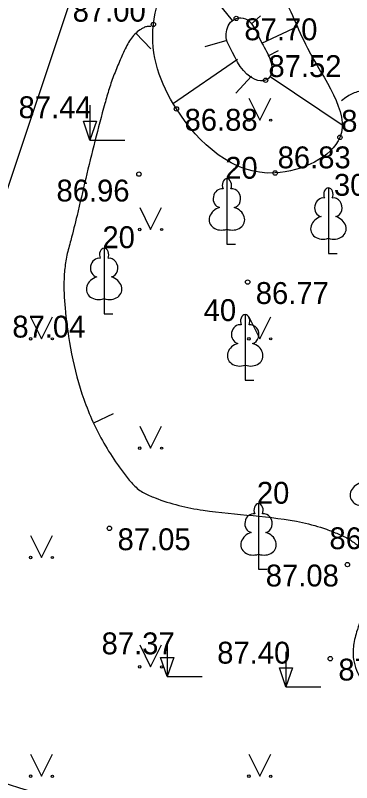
# Model space of a CAD drawing. Extents: x 576692 to 577659, y 273254 to 273799.
# Drawn here: x 577579.4 to 577587.1, y 273474.85 to 273492.4 of the extents above; entities that cross this region are included whole.
import ezdxf

# ---------------------------------------------------------------- set-up
doc = ezdxf.new("R2010")
doc.units = 0
for name, color, linetype in [('APGR_SARK_####_####_#', 7, 'Continuous'), ('CELI_TAKA_####_####_#', 7, 'Continuous'), ('GAZE_ELEM_####_####_#', 7, 'Continuous'), ('GEOD_SITP_####_TKST_#', 7, 'Continuous'), ('HIDT_REZV_####_TKST_#', 7, 'Continuous'), ('LKAN_ELEM_PAST_TKST_#', 7, 'Continuous'), ('RELJ_ELEM_####_####_#', 7, 'Continuous'), ('SAKT_ELEM_####_####_#', 7, 'Continuous')]:
    doc.layers.add(name, color=color, linetype=linetype)

msp = doc.modelspace()

# ---------------------------------------------------------------- linework, layer by layer
at = {"layer": 'CELI_TAKA_####_####_#'}
msp.add_lwpolyline([(577405.2, 273487.348), (577452.189, 273444.346), (577456.559, 273431.587), (577478.341, 273425.873), (577486.021, 273451.871), (577490.672, 273451.531), (577489.422, 273447.212), (577534.643, 273445.737), (577535.261, 273448.657), (577565.483, 273447.437), (577587.681, 273513.681), (577602.056, 273510.387), (577616.261, 273508.586), (577600.316, 273457.536), (577582.857, 273411.886)], dxfattribs=at)
at = {"layer": 'GAZE_ELEM_####_####_#'}
for p, q in [((577584.374, 273492.276), (577583.292, 273493.615)), ((577584.8, 273492.195), (577585.015, 273492.389)), ((577585.045, 273491.761), (577585.88, 273492.15)), ((577584.246, 273491.821), (577583.74, 273491.675)), ((577585.19, 273491.469), (577585.431, 273491.589)), ((577584.49, 273491.386), (577583.004, 273490.363)), ((577584.811, 273491.004), (577584.45, 273490.619)), ((577585.236, 273490.997), (577586.932, 273489.866))]:
    msp.add_line(p, q, dxfattribs=at)
msp.add_spline([(577585.045, 273491.761), (577584.946, 273491.975), (577584.674, 273492.316), (577584.461, 273492.327), (577584.3, 273492.194), (577584.24, 273491.842), (577584.324, 273491.65), (577584.896, 273490.928), (577585.132, 273490.912), (577585.246, 273491.014), (577585.246, 273491.356), (577585.045, 273491.761)], degree=3, dxfattribs=at)
at = {"layer": 'GEOD_SITP_####_TKST_#'}
for p, q in [((577582.507, 273491.629), (577582.162, 273491.991)), ((577581.644, 273483.285), (577581.19, 273483.075))]:
    msp.add_line(p, q, dxfattribs=at)
for points in [[(577583.144, 273499.137), (577583.833, 273498.666), (577584.196, 273498.357), (577584.348, 273498.172), (577584.469, 273497.968), (577584.689, 273497.451), (577584.886, 273496.935), (577585.096, 273496.425), (577585.352, 273495.926), (577585.521, 273495.668), (577585.622, 273495.549), (577585.742, 273495.438), (577586.297, 273495.12), (577586.897, 273494.983), (577587.193, 273494.971), (577587.489, 273494.982), (577587.785, 273494.998), (577588.081, 273495.001), (577588.596, 273494.934), (577589.109, 273494.81), (577589.619, 273494.7), (577589.872, 273494.672), (577589.999, 273494.669), (577590.125, 273494.674), (577590.318, 273494.721), (577590.408, 273494.77), (577590.494, 273494.839), (577590.628, 273495.017), (577590.683, 273495.217), (577590.755, 273496.357), (577590.811, 273497.592), (577590.863, 273497.846), (577590.914, 273497.968), (577590.98, 273498.087), (577591.132, 273498.277), (577591.322, 273498.418), (577591.659, 273498.578), (577592.004, 273498.713), (577592.357, 273498.812), (577592.717, 273498.865), (577594.021, 273498.804), (577594.245, 273498.727), (577594.465, 273498.642), (577594.895, 273498.449), (577597.047, 273497.335), (577597.802, 273496.866), (577597.99, 273496.746), (577598.086, 273496.7), (577598.186, 273496.683), (577598.881, 273496.773), (577599.58, 273496.97), (577600.282, 273497.202), (577600.635, 273497.308), (577600.988, 273497.397), (577601.285, 273497.465), (577601.582, 273497.54), (577602.177, 273497.692), (577602.774, 273497.816), (577603.075, 273497.858), (577603.378, 273497.881), (577603.698, 273497.87), (577603.769, 273497.867), (577603.904, 273497.862), (577603.97, 273497.851), (577604.035, 273497.824), (577604.253, 273497.675), (577604.447, 273497.506), (577604.75, 273497.093), (577605.115, 273496.124), (577605.373, 273495.082), (577605.539, 273494.584), (577605.77, 273494.129), (577606.025, 273493.738), (577606.322, 273493.373), (577606.563, 273493.171), (577606.832, 273493.008), (577607.412, 273492.744), (577607.99, 273492.479), (577608.254, 273492.316), (577608.489, 273492.114), (577608.663, 273491.921), (577608.845, 273491.698), (577610.478, 273490.111)], [(577582.506, 273492.14), (577582.477, 273492.143), (577582.398, 273492.137), (577582.325, 273492.105), (577582.257, 273492.065), (577582.137, 273491.965), (577581.958, 273491.708), (577581.804, 273491.381), (577581.668, 273491.052), (577581.55, 273490.72), (577581.451, 273490.38), (577581.013, 273488.663), (577580.814, 273487.822), (577580.67, 273487.251), (577580.623, 273487.078), (577580.551, 273486.739), (577580.518, 273486.398), (577580.516, 273486.059), (577580.539, 273485.721), (577580.691, 273484.655), (577580.971, 273483.617), (577581.428, 273482.615), (577581.739, 273482.13), (577581.918, 273481.891), (577582.113, 273481.656), (577582.344, 273481.476), (577582.47, 273481.417), (577582.601, 273481.364), (577583.144, 273481.191), (577583.704, 273481.082), (577584.846, 273480.958), (577585.98, 273480.799), (577586.528, 273480.646), (577586.795, 273480.54), (577587.056, 273480.411), (577587.253, 273480.26), (577587.413, 273480.058), (577587.521, 273479.873), (577587.574, 273479.681), (577587.571, 273479.451), (577587.529, 273479.221), (577587.378, 273478.76), (577587.216, 273478.298), (577587.144, 273477.949), (577587.137, 273477.833), (577587.158, 273477.61), (577587.24, 273477.368), (577587.358, 273477.137), (577587.477, 273476.908), (577587.565, 273476.676), (577587.634, 273476.375), (577587.684, 273476.06), (577587.704, 273475.412), (577587.576, 273474.769), (577587.442, 273474.462), (577587.354, 273474.314), (577587.252, 273474.171), (577586.832, 273473.799), (577586.344, 273473.556), (577586.135, 273473.469), (577585.924, 273473.395), (577585.393, 273473.232), (577585.066, 273473.15), (577584.797, 273473.139), (577584.573, 273473.155), (577584.271, 273473.203), (577583.947, 273473.282), (577582.992, 273473.544), (577580.904, 273474.297), (577577.343, 273475.704), (577575.937, 273477.173)], [(577589.179, 273485.7), (577589.17, 273485.918), (577589.131, 273486.319), (577589.069, 273486.689), (577588.996, 273487.058), (577588.921, 273487.425), (577588.851, 273487.794), (577588.789, 273488.172), (577588.735, 273488.55), (577588.682, 273488.93), (577588.624, 273489.308), (577588.554, 273489.639), (577588.448, 273489.959), (577588.298, 273490.266), (577588.203, 273490.414), (577588.094, 273490.557), (577587.988, 273490.647), (577587.926, 273490.68), (577587.86, 273490.706), (577587.713, 273490.732), (577587.567, 273490.726), (577587.266, 273490.658), (577587.006, 273490.542), (577586.87, 273490.441)]]:
    msp.add_spline(points, degree=3, dxfattribs=at)
at = {"layer": 'LKAN_ELEM_PAST_TKST_#'}
for p, q in [((577581.109, 273490.341), (577581.109, 273489.541)), ((577584.75, 273490.5), (577585, 273490)), ((577585, 273490), (577585.25, 273490.5)), ((577581.109, 273489.541), (577581.909, 273489.541)), ((577582.25, 273488), (577582.5, 273487.5)), ((577582.5, 273487.5), (577582.75, 273488)), ((577584.247, 273487.508), (577584.247, 273487.161)), ((577586.571, 273487.3), (577586.571, 273486.953)), ((577584.247, 273487.161), (577584.447, 273487.161)), ((577586.571, 273486.953), (577586.771, 273486.953)), ((577581.435, 273485.92), (577581.435, 273485.573)), ((577579.75, 273485.5), (577580, 273485)), ((577580, 273485), (577580.25, 273485.5)), ((577581.435, 273485.573), (577581.635, 273485.573)), ((577584.75, 273485.5), (577585, 273485)), ((577585, 273485), (577585.25, 273485.5)), ((577584.665, 273484.4), (577584.665, 273484.053)), ((577584.665, 273484.053), (577584.865, 273484.053)), ((577582.25, 273483), (577582.5, 273482.5)), ((577582.5, 273482.5), (577582.75, 273483)), ((577579.75, 273480.5), (577580, 273480)), ((577580, 273480), (577580.25, 273480.5)), ((577584.972, 273480.077), (577584.972, 273479.73)), ((577584.972, 273479.73), (577585.172, 273479.73)), ((577582.879, 273478.082), (577582.879, 273477.282)), ((577582.25, 273478), (577582.5, 273477.5)), ((577582.5, 273477.5), (577582.75, 273478)), ((577585.598, 273477.845), (577585.598, 273477.045)), ((577582.879, 273477.282), (577583.679, 273477.282)), ((577585.598, 273477.045), (577586.398, 273477.045)), ((577579.75, 273475.5), (577580, 273475)), ((577580, 273475), (577580.25, 273475.5)), ((577584.75, 273475.5), (577585, 273475)), ((577585, 273475), (577585.25, 273475.5))]:
    msp.add_line(p, q, dxfattribs=at)
for points in [[(577584.247, 273488.661), (577584.247, 273487.508)], [(577584.337, 273488.429), (577584.336, 273488.43)], [(577586.571, 273488.453), (577586.571, 273487.3)], [(577586.661, 273488.221), (577586.66, 273488.222)], [(577581.435, 273487.073), (577581.435, 273485.92)], [(577581.525, 273486.841), (577581.524, 273486.842)], [(577584.665, 273485.553), (577584.665, 273484.4)], [(577584.755, 273485.321), (577584.754, 273485.322)], [(577584.972, 273481.23), (577584.972, 273480.077)], [(577585.062, 273480.998), (577585.061, 273480.999)]]:
    msp.add_lwpolyline(points, dxfattribs=at)
for centre, radius in [((577584.75, 273490), 0.028), ((577585.25, 273490), 0.0263), ((577582.25, 273487.5), 0.028), ((577582.75, 273487.5), 0.0263), ((577579.75, 273485), 0.028), ((577580.25, 273485), 0.0263), ((577584.75, 273485), 0.028), ((577585.25, 273485), 0.0263), ((577582.25, 273482.5), 0.028), ((577582.75, 273482.5), 0.0263), ((577579.75, 273480), 0.028), ((577580.25, 273480), 0.0263), ((577582.25, 273477.5), 0.028), ((577582.75, 273477.5), 0.0263), ((577579.75, 273475), 0.028), ((577580.25, 273475), 0.0263), ((577584.75, 273475), 0.028), ((577585.25, 273475), 0.0263)]:
    msp.add_circle(centre, radius, dxfattribs=at)
for centre, major_axis, ratio, start_param, end_param in [((577584.247, 273488.511), (0, -0.15), 0.707107, 3.14537, 5.287485), ((577584.247, 273488.511), (0, -0.15), 0.707107, 0.995701, 3.137816), ((577584.119, 273488.216), (-0.039, -0.212), 0.861323, 3.141593, 6.283185), ((577584.375, 273488.216), (0.039, -0.212), 0.861323, 0, 3.141593), ((577586.571, 273488.303), (0, -0.15), 0.707107, 3.14537, 5.287485), ((577586.571, 273488.303), (0, -0.15), 0.707107, 0.995701, 3.137816), ((577586.443, 273488.008), (-0.039, -0.212), 0.861323, 3.141593, 6.283185), ((577586.699, 273488.008), (0.039, -0.212), 0.861323, 0, 3.141593), ((577584.157, 273487.754), (0.307, 0.095), 0.814445, 1.570796, 4.752015), ((577584.337, 273487.754), (-0.307, 0.095), 0.814445, 1.531171, 4.712389), ((577586.481, 273487.546), (0.307, 0.095), 0.814445, 1.570796, 4.752015), ((577586.661, 273487.546), (-0.307, 0.095), 0.814445, 1.531171, 4.712389), ((577581.435, 273486.923), (0, -0.15), 0.707107, 3.14537, 5.287485), ((577581.435, 273486.923), (0, -0.15), 0.707107, 0.995701, 3.137816), ((577581.307, 273486.628), (-0.039, -0.212), 0.861323, 3.141593, 6.283185), ((577581.563, 273486.628), (0.039, -0.212), 0.861323, 0, 3.141593), ((577581.345, 273486.166), (0.307, 0.095), 0.814445, 1.570796, 4.752015), ((577581.525, 273486.166), (-0.307, 0.095), 0.814445, 1.531171, 4.712389), ((577584.665, 273485.403), (0, -0.15), 0.707107, 3.14537, 5.287485), ((577584.665, 273485.403), (0, -0.15), 0.707107, 0.995701, 3.137816), ((577584.537, 273485.108), (-0.039, -0.212), 0.861323, 3.141593, 6.283185), ((577584.793, 273485.108), (0.039, -0.212), 0.861323, 0, 3.141593), ((577584.575, 273484.646), (0.307, 0.095), 0.814445, 1.570796, 4.752015), ((577584.755, 273484.646), (-0.307, 0.095), 0.814445, 1.531171, 4.712389), ((577587.385, 273481.455), (0.307, 0.095), 0.814445, 1.570796, 4.752015), ((577584.972, 273481.08), (0, -0.15), 0.707107, 3.14537, 5.287485), ((577584.972, 273481.08), (0, -0.15), 0.707107, 0.995701, 3.137816), ((577584.844, 273480.785), (-0.039, -0.212), 0.861323, 3.141593, 6.283185), ((577585.1, 273480.785), (0.039, -0.212), 0.861323, 0, 3.141593), ((577584.882, 273480.323), (0.307, 0.095), 0.814445, 1.570796, 4.752015), ((577585.062, 273480.323), (-0.307, 0.095), 0.814445, 1.531171, 4.712389)]:
    msp.add_ellipse(centre, major_axis=major_axis, ratio=ratio, start_param=start_param, end_param=end_param, dxfattribs=at)
at = {"layer": 'RELJ_ELEM_####_####_#'}
for points in [[(577580.959, 273489.974), (577581.259, 273489.974), (577581.109, 273489.541)], [(577582.729, 273477.715), (577583.029, 273477.715), (577582.879, 273477.282)], [(577585.448, 273477.478), (577585.748, 273477.478), (577585.598, 273477.045)]]:
    msp.add_lwpolyline(points, close=True, dxfattribs=at)
for centre in [(577584.461, 273492.327), (577582.564, 273492.189), (577585.132, 273490.912), (577583.091, 273490.258), (577586.835, 273489.607), (577582.231, 273488.766), (577585.352, 273488.792), (577584.722, 273486.297), (577581.557, 273480.667), (577587.008, 273479.838), (577586.614, 273477.687)]:
    msp.add_circle(centre, 0.05, dxfattribs=at)
at = {"layer": 'SAKT_ELEM_####_####_#'}
msp.add_spline([(577584.932, 273493.519), (577584.638, 273493.627), (577583.529, 273493.775), (577582.564, 273492.189), (577583.091, 273490.258), (577585.352, 273488.792), (577586.835, 273489.607), (577586.09, 273491.649), (577585.455, 273492.922), (577584.932, 273493.519)], degree=3, dxfattribs=at)

# ---------------------------------------------------------------- texts
at = {"layer": 'APGR_SARK_####_####_#'}
for s, p in [(' 20', (577584.022, 273488.661)), (' 30', (577586.512, 273488.271)), (' 20', (577581.21, 273487.073)), (' 40', (577583.529, 273485.407)), (' 20', (577584.747, 273481.23))]:
    msp.add_text(s, height=0.5, dxfattribs=at).set_placement(p)
at = {"layer": 'HIDT_REZV_####_TKST_#'}
for s, p in [(' 87.00', (577580.529, 273492.252)), (' 87.70', (577584.461, 273491.827)), (' 87.52', (577585.012, 273490.986)), (' 87.44', (577579.29, 273490.045)), (' 86.88', (577583.091, 273489.758)), (' 86.91', (577586.679, 273489.734)), (' 86.83', (577585.223, 273488.899)), (' 86.96', (577580.158, 273488.14)), (' 86.77', (577584.722, 273485.797)), (' 87.04', (577579.147, 273485.029)), (' 86.70', (577586.409, 273480.19)), (' 87.05', (577581.557, 273480.167)), (' 87.08', (577584.951, 273479.338)), (' 87.37', (577581.191, 273477.787)), (' 87.40', (577583.839, 273477.574)), (' 87.04', (577586.614, 273477.187))]:
    msp.add_text(s, height=0.5, dxfattribs=at).set_placement(p)

doc.saveas('drawing.dxf')
